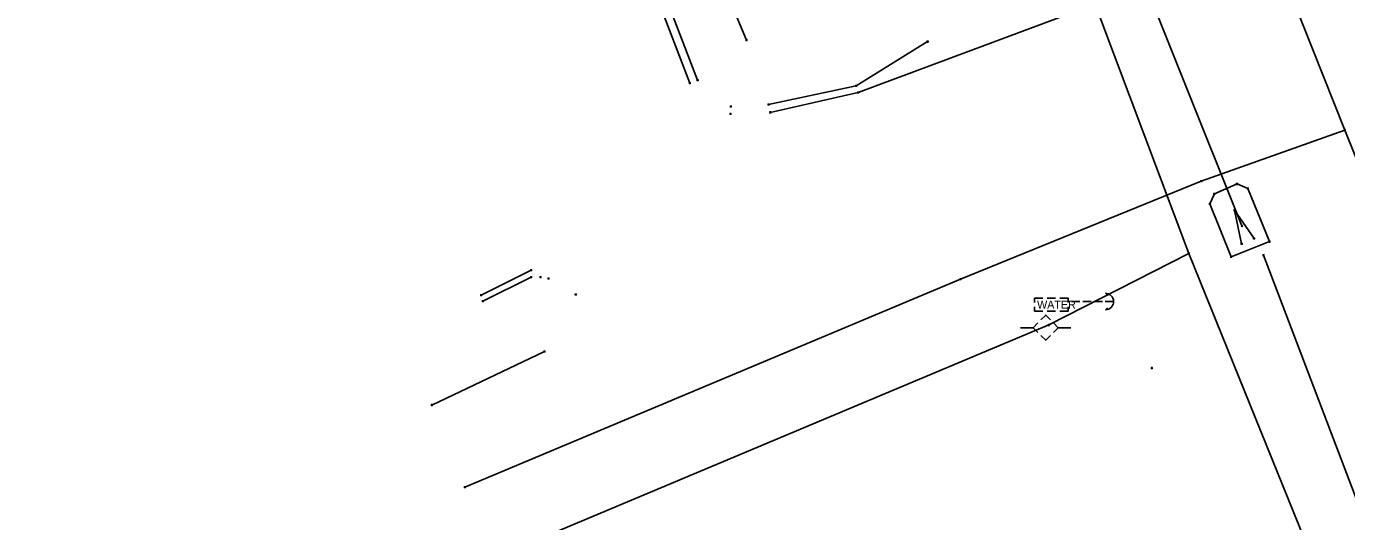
# Model space of a CAD drawing. Extents: x 1954856 to 2011933, y 399149 to 426294.
# Drawn here: x 2004673.3 to 2004830, y 408192 to 408250.7 of the extents above; entities that cross this region are included whole.
import ezdxf

# ---------------------------------------------------------------- set-up
doc = ezdxf.new("R2010")
doc.units = 0
for name, color, linetype in [('BankMent_ep', 7, 'Continuous'), ('CGBack_ep', 7, 'Continuous'), ('Driveway_ep', 7, 'Continuous'), ('ElecAer_ep', 7, 'Continuous'), ('EndTreatMES_ep', 7, 'Continuous'), ('FlowLineInvert_ep', 7, 'Continuous'), ('GuyWireAnchor_ep', 7, 'Continuous'), ('MeterWater_ep', 7, 'Continuous'), ('PipeCulvert_ep', 7, 'Continuous'), ('PointLocator_ep', 7, 'Continuous'), ('PoleElec_ep', 7, 'Continuous'), ('ShldrPaved_ep', 7, 'Continuous')]:
    doc.layers.add(name, color=color, linetype=linetype)

msp = doc.modelspace()

# ---------------------------------------------------------------- linework, layer by layer
at = {"layer": 'BankMent_ep'}
for points in [[(2004725.72, 408333.95), (2004726.03, 408327.25), (2004758.77, 408249.11)], [(2004897.29, 408037.55), (2004891.88, 408049.97), (2004851.38, 408141.51), (2004820.13, 408223.57)]]:
    msp.add_lwpolyline(points, dxfattribs=at)
at = {"layer": 'CGBack_ep'}
for p, q in [((2004737.44, 408284.76), (2004752.97, 408244.36)), ((2004771.79, 408243.68), (2004780.27, 408248.92)), ((2004761.4, 408241.46), (2004771.79, 408243.68)), ((2004727.49, 408218.13), (2004733.22, 408220.98))]:
    msp.add_line(p, q, dxfattribs=at)
at = {"layer": 'Driveway_ep'}
for p, q in [((2004752.04, 408244), (2004720.44, 408327.3)), ((2004802.95, 408254.44), (2004772.03, 408242.89)), ((2004772.03, 408242.89), (2004761.6, 408240.53)), ((2004727.28, 408218.86), (2004733.21, 408221.82)), ((2004734.81, 408212.16), (2004721.44, 408205.8))]:
    msp.add_line(p, q, dxfattribs=at)
msp.add_lwpolyline([(2004829.78, 408238.43), (2004812.74, 408232.37), (2004784.17, 408220.74), (2004725.35, 408196.07)], dxfattribs=at)
at = {"layer": 'ElecAer_ep'}
for points in [[(2004811.27, 408223.79), (2004783.16, 408298.48), (2004697.45, 408511.41), (2004673.32, 408519.34), (2004627.85, 408504.91)], [(2004893.49, 408020.69), (2004811.27, 408223.79), (2004794.66, 408215.31), (2004729.32, 408187.88)]]:
    msp.add_lwpolyline(points, dxfattribs=at)
at = {"layer": 'EndTreatMES_ep'}
msp.add_lwpolyline([(2004820.84, 408225.19), (2004816.28, 408223.38), (2004813.76, 408229.69), (2004814.29, 408230.87), (2004816.99, 408232.04), (2004818.27, 408231.49)], close=True, dxfattribs=at)
msp.add_lwpolyline([(2004817.53, 408224.95), (2004816.7, 408228.91), (2004819, 408225.55)], dxfattribs=at)
at = {"layer": 'FlowLineInvert_ep'}
for p, q in [((2004817.66, 408226.96), (2004817.48, 408227.14)), ((2004817.66, 408227.14), (2004817.48, 408226.96)), ((2004817.57, 408227.05), (2004817.57, 408227.05))]:
    msp.add_line(p, q, dxfattribs=at)
at = {"layer": 'GuyWireAnchor_ep'}
for p, q in [((2004801.37, 408219.07), (2004801.56, 408218.87)), ((2004797.34, 408218.1), (2004798.34, 408218.1)), ((2004798.67, 408218.1), (2004799.67, 408218.1)), ((2004800.01, 408218.1), (2004801.01, 408218.1)), ((2004801.34, 408218.09), (2004802.34, 408218.09)), ((2004802.34, 408218.09), (2004802.34, 408218.09)), ((2004801.38, 408217.12), (2004801.62, 408217.35))]:
    msp.add_line(p, q, dxfattribs=at)
msp.add_arc((2004801.37, 408218.09), 0.973, 271.14, 90.0059, dxfattribs=at)
at = {"layer": 'MeterWater_ep'}
msp.add_line((2004794.95, 408217.71), (2004794.95, 408217.71), dxfattribs=at)
for points in [[(2004792.95, 408217.96), (2004792.95, 408218.47), (2004793.95, 408218.47)], [(2004793.95, 408216.96), (2004792.95, 408216.96), (2004792.95, 408217.46)], [(2004794.45, 408218.47), (2004795.45, 408218.47)], [(2004795.95, 408218.47), (2004796.95, 408218.47), (2004796.95, 408217.96)], [(2004796.95, 408217.46), (2004796.95, 408216.96), (2004795.95, 408216.96)], [(2004795.45, 408216.96), (2004794.45, 408216.96)]]:
    msp.add_lwpolyline(points, dxfattribs=at)
at = {"layer": 'PipeCulvert_ep'}
msp.add_lwpolyline([(2004803.24, 408262.87), (2004817.57, 408227.05)], dxfattribs=at)
at = {"layer": 'PointLocator_ep'}
for p, q in [((2004758.89, 408249.11), (2004758.64, 408249.11)), ((2004758.77, 408248.99), (2004758.77, 408249.24)), ((2004758.77, 408249.11), (2004758.77, 408249.11)), ((2004780.4, 408248.92), (2004780.15, 408248.92)), ((2004780.27, 408248.8), (2004780.27, 408249.05)), ((2004780.27, 408248.92), (2004780.27, 408248.92)), ((2004752.04, 408243.88), (2004752.04, 408244.13)), ((2004753.1, 408244.36), (2004752.85, 408244.36)), ((2004752.97, 408244.23), (2004752.97, 408244.48)), ((2004752.97, 408244.36), (2004752.97, 408244.36)), ((2004752.16, 408244), (2004751.91, 408244)), ((2004752.04, 408244), (2004752.04, 408244)), ((2004771.91, 408243.68), (2004771.66, 408243.68)), ((2004771.79, 408243.55), (2004771.79, 408243.8)), ((2004771.79, 408243.68), (2004771.79, 408243.68)), ((2004772.16, 408242.89), (2004771.91, 408242.89)), ((2004772.03, 408242.77), (2004772.03, 408243.02)), ((2004772.03, 408242.89), (2004772.03, 408242.89)), ((2004757.04, 408241.23), (2004756.79, 408241.23)), ((2004756.91, 408241.11), (2004756.91, 408241.36)), ((2004756.91, 408241.23), (2004756.91, 408241.23)), ((2004761.53, 408241.46), (2004761.28, 408241.46)), ((2004761.4, 408241.34), (2004761.4, 408241.59)), ((2004761.4, 408241.46), (2004761.4, 408241.46)), ((2004756.99, 408240.35), (2004756.74, 408240.35)), ((2004756.86, 408240.23), (2004756.86, 408240.48)), ((2004756.86, 408240.35), (2004756.86, 408240.35)), ((2004761.73, 408240.53), (2004761.48, 408240.53)), ((2004761.6, 408240.41), (2004761.6, 408240.66)), ((2004761.6, 408240.53), (2004761.6, 408240.53)), ((2004829.91, 408238.43), (2004829.66, 408238.43)), ((2004829.78, 408238.31), (2004829.78, 408238.56)), ((2004829.78, 408238.43), (2004829.78, 408238.43)), ((2004812.87, 408232.37), (2004812.62, 408232.37)), ((2004812.74, 408232.25), (2004812.74, 408232.5)), ((2004812.74, 408232.37), (2004812.74, 408232.37)), ((2004817.11, 408232.04), (2004816.86, 408232.04)), ((2004816.99, 408231.91), (2004816.99, 408232.16)), ((2004816.99, 408232.04), (2004816.99, 408232.04)), ((2004818.27, 408231.37), (2004818.27, 408231.62)), ((2004814.42, 408230.87), (2004814.17, 408230.87)), ((2004814.29, 408230.75), (2004814.29, 408231)), ((2004814.29, 408230.87), (2004814.29, 408230.87)), ((2004818.4, 408231.49), (2004818.15, 408231.49)), ((2004818.27, 408231.49), (2004818.27, 408231.49)), ((2004813.89, 408229.69), (2004813.64, 408229.69)), ((2004813.76, 408229.56), (2004813.76, 408229.81)), ((2004813.76, 408229.69), (2004813.76, 408229.69)), ((2004816.82, 408228.91), (2004816.57, 408228.91)), ((2004816.7, 408228.78), (2004816.7, 408229.03)), ((2004816.7, 408228.91), (2004816.7, 408228.91)), ((2004819.12, 408225.55), (2004818.87, 408225.55)), ((2004819, 408225.43), (2004819, 408225.68)), ((2004819, 408225.55), (2004819, 408225.55)), ((2004820.84, 408225.06), (2004820.84, 408225.31)), ((2004811.4, 408223.79), (2004811.15, 408223.79)), ((2004811.27, 408223.67), (2004811.27, 408223.92)), ((2004811.27, 408223.79), (2004811.27, 408223.79)), ((2004817.66, 408224.95), (2004817.41, 408224.95)), ((2004817.53, 408224.83), (2004817.53, 408225.08)), ((2004817.53, 408224.95), (2004817.53, 408224.95)), ((2004820.96, 408225.19), (2004820.71, 408225.19)), ((2004820.84, 408225.19), (2004820.84, 408225.19)), ((2004816.4, 408223.38), (2004816.15, 408223.38)), ((2004816.28, 408223.26), (2004816.28, 408223.51)), ((2004816.28, 408223.38), (2004816.28, 408223.38)), ((2004820.25, 408223.57), (2004820, 408223.57)), ((2004820.13, 408223.44), (2004820.13, 408223.69)), ((2004820.13, 408223.57), (2004820.13, 408223.57)), ((2004733.34, 408221.82), (2004733.09, 408221.82)), ((2004733.34, 408220.98), (2004733.09, 408220.98)), ((2004733.21, 408221.69), (2004733.21, 408221.94)), ((2004733.21, 408221.82), (2004733.21, 408221.82)), ((2004733.22, 408220.86), (2004733.22, 408221.11)), ((2004733.22, 408220.98), (2004733.22, 408220.98)), ((2004734.44, 408220.98), (2004734.19, 408220.98)), ((2004734.31, 408220.85), (2004734.31, 408221.1)), ((2004734.31, 408220.98), (2004734.31, 408220.98)), ((2004735.41, 408220.83), (2004735.16, 408220.83)), ((2004735.28, 408220.7), (2004735.28, 408220.95)), ((2004735.28, 408220.83), (2004735.28, 408220.83)), ((2004784.29, 408220.74), (2004784.04, 408220.74)), ((2004784.17, 408220.61), (2004784.17, 408220.86)), ((2004784.17, 408220.74), (2004784.17, 408220.74)), ((2004738.51, 408218.8), (2004738.51, 408219.05)), ((2004727.4, 408218.86), (2004727.15, 408218.86)), ((2004727.28, 408218.73), (2004727.28, 408218.98)), ((2004727.28, 408218.86), (2004727.28, 408218.86)), ((2004727.61, 408218.13), (2004727.36, 408218.13)), ((2004727.49, 408218.01), (2004727.49, 408218.26)), ((2004727.49, 408218.13), (2004727.49, 408218.13)), ((2004738.63, 408218.92), (2004738.38, 408218.92)), ((2004738.51, 408218.92), (2004738.51, 408218.92)), ((2004794.78, 408215.31), (2004794.53, 408215.31)), ((2004794.66, 408215.18), (2004794.66, 408215.43)), ((2004794.66, 408215.31), (2004794.66, 408215.31)), ((2004734.94, 408212.16), (2004734.69, 408212.16)), ((2004734.81, 408212.03), (2004734.81, 408212.28)), ((2004734.81, 408212.16), (2004734.81, 408212.16)), ((2004807.01, 408210.2), (2004806.76, 408210.2)), ((2004806.89, 408210.07), (2004806.89, 408210.32)), ((2004806.89, 408210.2), (2004806.89, 408210.2)), ((2004721.57, 408205.8), (2004721.32, 408205.8)), ((2004721.44, 408205.68), (2004721.44, 408205.93)), ((2004721.44, 408205.8), (2004721.44, 408205.8)), ((2004725.47, 408196.07), (2004725.22, 408196.07)), ((2004725.35, 408195.95), (2004725.35, 408196.2)), ((2004725.35, 408196.07), (2004725.35, 408196.07))]:
    msp.add_line(p, q, dxfattribs=at)
at = {"layer": 'PoleElec_ep'}
for p, q in [((2004791.29, 408214.98), (2004792.79, 408214.98)), ((2004792.79, 408214.98), (2004793.36, 408215.55)), ((2004793.36, 408214.41), (2004792.79, 408214.98)), ((2004794.28, 408214.98), (2004794.28, 408214.98)), ((2004797.27, 408214.98), (2004795.77, 408214.98))]:
    msp.add_line(p, q, dxfattribs=at)
for points in [[(2004793.71, 408215.9), (2004794.28, 408216.47), (2004794.85, 408215.9)], [(2004795.2, 408215.55), (2004795.77, 408214.98), (2004795.2, 408214.41)], [(2004794.85, 408214.06), (2004794.28, 408213.49), (2004793.71, 408214.06)]]:
    msp.add_lwpolyline(points, dxfattribs=at)
at = {"layer": 'ShldrPaved_ep'}
msp.add_lwpolyline([(2004903.29, 408054.42), (2004866.25, 408147.18), (2004829.78, 408238.43), (2004819.43, 408264.53), (2004792.12, 408332.81), (2004764.06, 408411.25), (2004736.07, 408472.39), (2004723.51, 408503.89), (2004692.56, 408581.58), (2004685.95, 408598.81), (2004662.72, 408655.96), (2004643.53, 408704.54), (2004611.46, 408784.57), (2004586.66, 408847.41), (2004569.7, 408890.52), (2004561.67, 408910.22), (2004521.28, 409011.51), (2004496.04, 409076.36), (2004458.97, 409168.82), (2004421.59, 409262.3), (2004384.82, 409355.23), (2004347.84, 409447.99), (2004310.72, 409540.77), (2004273.84, 409633.55)], dxfattribs=at)

# ---------------------------------------------------------------- texts
at = {"layer": 'MeterWater_ep'}
msp.add_text('WATER', height=0.95, dxfattribs=at).set_placement((2004793.26, 408217.24))

doc.saveas('drawing.dxf')
